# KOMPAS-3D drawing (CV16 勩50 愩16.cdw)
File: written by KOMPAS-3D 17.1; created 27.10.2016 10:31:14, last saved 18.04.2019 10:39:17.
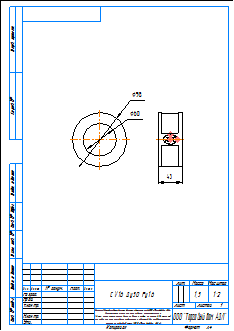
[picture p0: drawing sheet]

Sheet 1: A4, portrait

Title block, sheet 1: name: CV16 Ду50 Ру16; material: Сталь 20  ГОСТ 1050-88; mass: 1,5; sheets: 1; sheet format: A4; stored path: \\adlc.lan\data\АДЛ_ПКД\3D-модели\ADL production\Клапаны обратные ГРАНЛОК\CV16\KOMPAS 2D\CV16 Ду50 Ру16.cdw

Views: Вид 1, Проекционный вид 2
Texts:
  Klimkovich
  ADL
  Рама для чертежей
  Лит-Масса-Масштаб
  Материал-Предприятие
  Масштаб
  Изм.
  Лист
  № докум.
  Подп.
  Дата
  Лит.
  Разраб.
  Пров.
  Т.контр.
  Листов
  Внимание! Данный продукт является объектом авторского права ООО «Торговый Дом АДЛ».
  Запрещается изменение, копирование, распространение
  (в том числе путем копирования на другие сайты и ресурсы в Интернете)
  или любое иное использование информации и объектов без предварительного
  согласия правообладателя (ООО «Торговый Дом АДЛ»).
  Н.контр.
  Утв.
  ООО "Торговый дом АДЛ"
  Изменение
  Номер документа
  Подпись
  Обозначение документа
  Наименование изделия
  Масса изделия по ГОСТ 2.109-73
  Порядковый номер листа
  Общее количество листов в документе
  Характер работы, выполненной лицом, подписавшим документ
  Наименование или индекс предприятия, выпускающего документ
  Инв. № подл.
  Подп. и дата
  Взам. инв. №
  Инв. № дубл.
  Инвентарный номер подлинника по ГОСТ 2.501-68
  Подпись принявшего подлинник в отдел технической документации
  Инвентарный номер подлинника, взамен которого выпущен данный подлинник
  Инвентарный номер дубликата по ГОСТ 2.502-68
  Подпись принявшего дубликат в отдел технической документации
  Справ. №
  Перв. примен.
  Обозначение документа, взамен или на основании которого выпущен данный документ
  Обозначение документа, в котором впервые записан данный документ
  Подпись лица, копировавшего чертеж
  Обозначение формата листа
  !Рама для чертежа
Dimensions and other numbers on the sheet: 98; 60; 43; 1:2; 1; 1,5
